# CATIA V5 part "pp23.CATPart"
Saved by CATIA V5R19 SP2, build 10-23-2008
Part number: pp23
Bounding box of the stored display mesh (mm): x -20 to 20, y -467.83 to -397.996, z -79.239 to 79.239
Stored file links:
  C:\Users\Welcome\Documents\thinkm2\pp23.CATPart
  C:\Users\Welcome\Documents\thinkm2\Brasmeca.CATProduct
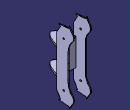
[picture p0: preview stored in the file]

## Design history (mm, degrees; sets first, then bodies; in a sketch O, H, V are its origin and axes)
External parameters (linked from other documents)
  External.Length.2 = 15.677 mm
  External.Length.3 = 10.679 mm
  External.Length.1 = 25.952 mm
  External.Length.4 = 11.712 mm
  External.poche1 = 21 mm
  External.Length.5 = 32.353 mm
AxisSystem1: origin (0, 0, 0), X (1, 0, 0), Y (0, 1, 0), Z (0, 0, 1)
Set1
  Plane1: linked copy from another document
  Line1: linked copy from another document
  Line2: linked copy from another document
  Sketch1, origin (5, 0, 0), H (0, 1, 0), V (0, 0, 1), geometry linked from another document
  Sketch2, origin (5, 0, 0), H (0, 1, 0), V (0, 0, 1), geometry linked from another document
Body1 (main body)
  Plane2: type Offset, RefPlane YZ plane of AxisSystem1, Offset 20
  Sketch3 on Plane2, origin (20, 0, 0), H (0, 1, 0), V (0, 0, 1)
    line L1 (-409.725, 24.9841) -> (-409.725, 6.56)
    line L2 (-435.677, 50.079) -> (-435.677, 16.4073)
    line L3 (-431.4452, 62.6098) -> (-426.9019, 70.5105)
    line L4 (-426.9019, 70.5105) -> (-431.0398, 72.89)
    line L5 (-431.0398, 72.89) -> (-407.7424, 75.2553)
    line L6 (-407.7424, 75.2553) -> (-407.7424, 79.2389)
    line L7 (-407.7424, 79.2389) -> (-399.5217, 65.6078)
    line L8 (-400.0043, 53.847) -> (-404.4339, 47.7038)
    line L9 (-409.725, 31.3188) -> (-409.725, 24.9841)
    arc A1 centre (-408.6664, 60.0928) radius 10.679 from (-399.5217, 65.6078) to (-400.0043, 53.847) cw
    arc A2 centre (-381.7099, 31.3188) radius 28.0151 from (-404.4339, 47.7038) to (-409.725, 31.3188) ccw
    reference projected line E1 (-420, 50) -> (-420, -50) from Line1
    line L10 (-435.677, 50.079) -> (-435.677, 52.1234)
    line L11 (-434.118, 57.9618) -> (-431.4452, 62.6098)
    arc A3 centre (-423.965, 52.1234) radius 11.712 from (-434.118, 57.9618) to (-435.677, 52.1234) ccw
    line L12 (-435.677, -50.079) -> (-435.677, -16.4073)
    arc A4 centre (-423.965, -52.1234) radius 11.712 from (-434.118, -57.9618) to (-435.677, -52.1234) cw
    line L13 (-435.677, -50.079) -> (-435.677, -52.1234)
    line L14 (-434.118, -57.9618) -> (-431.4452, -62.6098)
    line L15 (-431.4452, -62.6098) -> (-426.9019, -70.5105)
    line L16 (-426.9019, -70.5105) -> (-431.0398, -72.89)
    line L17 (-431.0398, -72.89) -> (-407.7424, -75.2553)
    line L18 (-407.7424, -75.2553) -> (-407.7424, -79.2389)
    line L19 (-407.7424, -79.2389) -> (-399.5217, -65.6078)
    arc A5 centre (-408.6664, -60.0928) radius 10.679 from (-399.5217, -65.6078) to (-400.0043, -53.847) ccw
    line L20 (-400.0043, -53.847) -> (-404.4339, -47.7038)
    arc A6 centre (-381.7099, -31.3188) radius 28.0151 from (-404.4339, -47.7038) to (-409.725, -31.3188) cw
    line L21 (-409.725, -31.3188) -> (-409.725, -24.9841)
    line L22 (-409.725, -24.9841) -> (-409.725, -6.56)
    line L23 (-435.677, 16.4073) -> (-435.677, -16.4073)
    line L24 (-409.725, 6.56) -> (-409.725, -6.56)
    distance L1 L2 = 25.952 {= External.Length.1}
    distance E1 L2 = 15.677 {= External.Length.2}
    radius A1 = 10.679 {= External.Length.3}
    radius A3 = 11.712 {= External.Length.4}
    distance E1 L12 = 15.677
    distance L22 L12 = 25.952
    radius A5 = 10.679
    radius A4 = 11.712
  Sketch4 on Plane1, origin (0, -420, 0), H (-1, 0, 0), V (0, 0, 1)
    line L1 (-18, 90) -> (-18, 30)
    line L2 (-18, 30) -> (18, 30)
    line L3 (18, 30) -> (18, 90)
    line L4 (18, 90) -> (20, 90)
    line L5 (20, 90) -> (20, -90)
    line L6 (20, -90) -> (18, -90)
    line L7 (18, -90) -> (18, -30)
    line L8 (18, -30) -> (-18, -30)
    line L9 (-18, -30) -> (-18, -90)
    line L10 (-18, -90) -> (-20, -90)
    line L11 (-20, -90) -> (-20, 90)
    line L12 (-18, 90) -> (-20, 90)
    distance L2 H = 30
    distance L2 L8 = 60
    distance L5 L11 = 40
    distance L5 V = 20
    distance L3 L5 = 2
    distance L1 L11 = 2
    distance L4 L2 = 60
    distance L12 L2 = 60
    distance L5 L7 = 2
    distance L9 L11 = 2
    distance L6 L8 = 60
    distance L10 L8 = 60
  SolidCombine1: FirstComponentProfile Sketch3, FirstComponentDirection Sketch3, SecondComponentProfile Sketch4, SecondComponentDirection Sketch4
  Sketch5 on face of SolidCombine1 from Sketch3.L1, origin (0, -409.725, 0), H (-1, 0, 0), V (0, 0, 1)
    line L1 (-18, 30) -> (18, 30)
    line L2 (18, 30) -> (18, -30)
    line L3 (18, -30) -> (-18, -30)
    line L4 (-18, -30) -> (-18, 30)
    distance L1 H = 30
    distance L1 L3 = 60
    distance L2 L4 = 36
    distance L2 V = 18
  Pocket1: profile Sketch5, direction (0, -1, 0), length 21 {= External.poche1}
  Sketch6 on face of SolidCombine1 from Sketch4.L2, origin (0, 0, 30), H (1, 0, 0), V (0, 1, 0)
    spline S1 through (-19.9685, -435.6057) (0, -467.9587) (20.0321, -435.6057)
    line L1 (20.0321, -435.6057) -> (-19.9685, -435.6057)
    point P1 (20.0321, -435.6057)
    point P2 (-19.9685, -435.6057)
    point P3 (20.0321, -435.6057)
    point P4 (-19.9685, -435.6057)
    point P5 (0, -467.9587)
    distance P5 L1 = 32.353 {= External.Length.5}
    coincidence: P3 P1, P4 P2
  Sketch7 on face of SolidCombine1 from Sketch3.L2, origin (0, -435.677, 0), H (1, 0, 0), V (0, 0, 1)
    line L1 (-20, 30) -> (20, 30)
    line L2 (20, 30) -> (20, 26)
    line L3 (20, 26) -> (-20, 26)
    line L4 (-20, 26) -> (-20, 30)
    distance L2 L4 = 40
    distance L2 V = 20
    distance L1 H = 30
    distance L3 H = 26
  SolidCombine2: FirstComponentProfile Sketch6, FirstComponentDirection Sketch6, SecondComponentProfile Sketch7, SecondComponentDirection Sketch7
  Mirror1: of SolidCombine2, about XY plane of AxisSystem1
  Pocket2: profile Sketch1, direction (1, 0, 0), length 21
  Pocket3: profile Sketch1, direction (-1, 0, 0), length 46
  Pocket4: profile Sketch2, direction (1, 0, 0), length 46
  Pocket5: profile Sketch2, direction (-1, 0, 0), length 46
